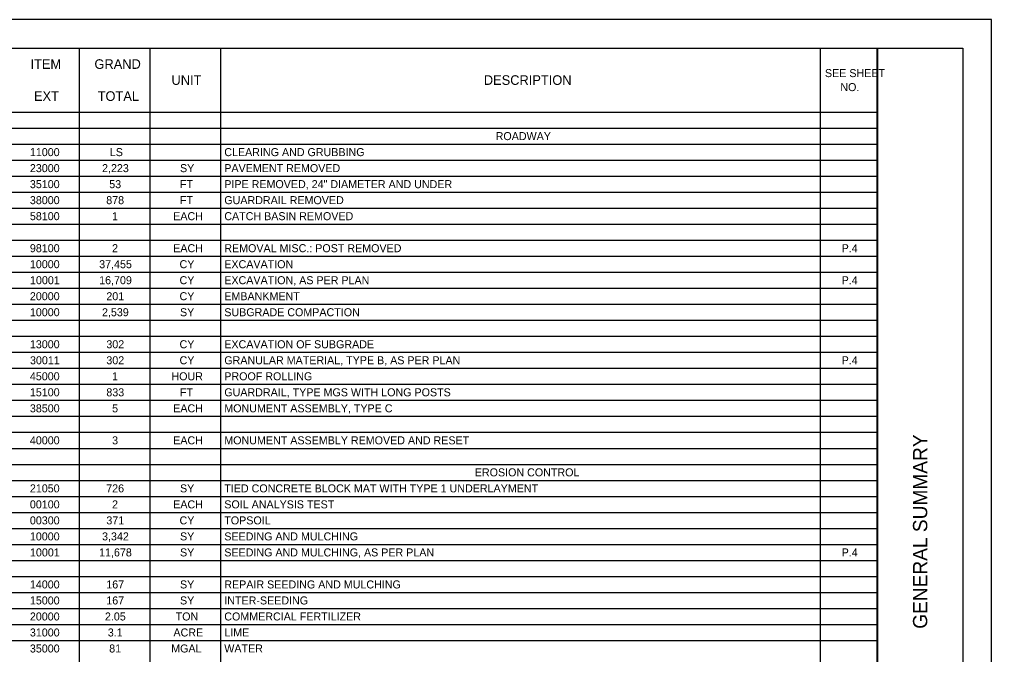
# Model space of a CAD drawing. Extents: x 0 to 34, y 0 to 22.
# Drawn here: x 16.99 to 34, y 10.89 to 22 of the extents above; entities that cross this region are included whole.
import ezdxf

# ---------------------------------------------------------------- set-up
doc = ezdxf.new("R2010")
doc.units = 0
for name, color, linetype in [('SH_Border', 7, 'Continuous'), ('SH_Cut_Line', 7, 'Continuous'), ('SH_Data', 7, 'Continuous'), ('SH_Text', 7, 'Continuous')]:
    doc.layers.add(name, color=color, linetype=linetype)

msp = doc.modelspace()

# ---------------------------------------------------------------- linework, layer by layer
at = {"layer": 'SH_Border'}
msp.add_line((32, 0.5), (32, 21.5), dxfattribs=at)
msp.add_lwpolyline([(1.5, 21.5), (33.5, 21.5), (33.5, 0.5), (1.5, 0.5)], close=True, dxfattribs=at)
at = {"layer": 'SH_Cut_Line'}
msp.add_lwpolyline([(0, 0), (34, 0), (34, 22), (0, 22)], close=True, dxfattribs=at)
at = {"layer": 'SH_Data'}
for p, q in [((1.5, 21.5), (32.004, 21.5)), ((18.036, 21.5), (18.036, 0.5)), ((19.272, 21.5), (19.272, 0.5)), ((20.507, 21.5), (20.507, 0.5)), ((30.999, 21.5), (30.999, 0.5)), ((32.004, 21.5), (32.004, 0.5)), ((1.5, 20.38), (32.004, 20.38)), ((1.5, 20.1), (32.004, 20.1)), ((1.5, 19.82), (32.004, 19.82)), ((1.5, 19.54), (32.004, 19.54)), ((1.5, 19.26), (32.004, 19.26)), ((1.5, 18.98), (32.004, 18.98)), ((1.5, 18.7), (32.004, 18.7)), ((1.5, 18.42), (32.004, 18.42)), ((1.5, 18.14), (32.004, 18.14)), ((1.5, 17.86), (32.004, 17.86)), ((1.5, 17.58), (32.004, 17.58)), ((1.5, 17.3), (32.004, 17.3)), ((1.5, 17.02), (32.004, 17.02)), ((1.5, 16.74), (32.004, 16.74)), ((1.5, 16.46), (32.004, 16.46)), ((1.5, 16.18), (32.004, 16.18)), ((1.5, 15.9), (32.004, 15.9)), ((1.5, 15.62), (32.004, 15.62)), ((1.5, 15.34), (32.004, 15.34)), ((1.5, 15.06), (32.004, 15.06)), ((1.5, 14.78), (32.004, 14.78)), ((1.5, 14.5), (32.004, 14.5)), ((1.5, 14.22), (32.004, 14.22)), ((1.5, 13.94), (32.004, 13.94)), ((1.5, 13.66), (32.004, 13.66)), ((1.5, 13.38), (32.004, 13.38)), ((1.5, 13.1), (32.004, 13.1)), ((1.5, 12.82), (32.004, 12.82)), ((1.5, 12.54), (32.004, 12.54)), ((1.5, 12.26), (32.004, 12.26)), ((1.5, 11.98), (32.004, 11.98)), ((1.5, 11.7), (32.004, 11.7)), ((1.5, 11.42), (32.004, 11.42)), ((1.5, 11.14), (32.004, 11.14))]:
    msp.add_line(p, q, dxfattribs=at)

# ---------------------------------------------------------------- texts
msp.add_text('GENERAL SUMMARY', height=0.25, rotation=90, dxfattribs=at).set_placement((32.875, 11.344))
at = {"layer": 'SH_Text'}
for s, height, p in [('ITEM', 0.168, (17.181, 21.136)), ('GRAND', 0.168, (18.301, 21.136)), ('SEE SHEET ', 0.14, (31.084, 20.992)), ('UNIT', 0.168, (19.649, 20.856)), ('DESCRIPTION', 0.168, (25.115, 20.856)), ('NO.', 0.14, (31.354, 20.747)), ('EXT', 0.168, (17.242, 20.576)), ('TOTAL', 0.168, (18.357, 20.576)), ('ROADWAY', 0.14, (25.322, 19.89)), ('11000', 0.14, (17.171, 19.61)), ('LS', 0.14, (18.57, 19.61)), ('CLEARING AND GRUBBING', 0.14, (20.573, 19.61)), ('23000', 0.14, (17.171, 19.33)), ('2,223', 0.14, (18.434, 19.33)), ('SY', 0.14, (19.798, 19.33)), ('PAVEMENT REMOVED', 0.14, (20.573, 19.33)), ('35100', 0.14, (17.171, 19.05)), ('53', 0.14, (18.56, 19.05)), ('FT', 0.14, (19.796, 19.05)), ('PIPE REMOVED, 24" DIAMETER AND UNDER', 0.14, (20.573, 19.05)), ('38000', 0.14, (17.171, 18.77)), ('878', 0.14, (18.507, 18.77)), ('FT', 0.14, (19.796, 18.77)), ('GUARDRAIL REMOVED', 0.14, (20.573, 18.77)), ('58100', 0.14, (17.171, 18.49)), ('1', 0.14, (18.609, 18.49)), ('EACH', 0.14, (19.679, 18.49)), ('CATCH BASIN REMOVED', 0.14, (20.573, 18.49)), ('98100', 0.14, (17.171, 17.93)), ('2', 0.14, (18.609, 17.93)), ('EACH', 0.14, (19.679, 17.93)), ('REMOVAL MISC.: POST REMOVED', 0.14, (20.573, 17.93)), ('P.4', 0.14, (31.377, 17.93)), ('10000', 0.14, (17.171, 17.65)), ('37,455', 0.14, (18.384, 17.65)), ('CY', 0.14, (19.79, 17.65)), ('EXCAVATION', 0.14, (20.573, 17.65)), ('10001', 0.14, (17.173, 17.37)), ('16,709', 0.14, (18.383, 17.37)), ('CY', 0.14, (19.79, 17.37)), ('EXCAVATION, AS PER PLAN', 0.14, (20.573, 17.37)), ('P.4', 0.14, (31.377, 17.37)), ('20000', 0.14, (17.171, 17.09)), ('201', 0.14, (18.509, 17.09)), ('CY', 0.14, (19.79, 17.09)), ('EMBANKMENT', 0.14, (20.573, 17.09)), ('10000', 0.14, (17.171, 16.81)), ('2,539', 0.14, (18.433, 16.81)), ('SY', 0.14, (19.798, 16.81)), ('SUBGRADE COMPACTION', 0.14, (20.573, 16.81)), ('13000', 0.14, (17.171, 16.25)), ('302', 0.14, (18.509, 16.25)), ('CY', 0.14, (19.79, 16.25)), ('EXCAVATION OF SUBGRADE', 0.14, (20.573, 16.25)), ('30011', 0.14, (17.173, 15.97)), ('302', 0.14, (18.509, 15.97)), ('CY', 0.14, (19.79, 15.97)), ('GRANULAR MATERIAL, TYPE B, AS PER PLAN', 0.14, (20.573, 15.97)), ('P.4', 0.14, (31.377, 15.97)), ('45000', 0.14, (17.171, 15.69)), ('1', 0.14, (18.609, 15.69)), ('HOUR', 0.14, (19.648, 15.69)), ('PROOF ROLLING', 0.14, (20.573, 15.69)), ('15100', 0.14, (17.171, 15.41)), ('833', 0.14, (18.509, 15.41)), ('FT', 0.14, (19.796, 15.41)), ('GUARDRAIL, TYPE MGS WITH LONG POSTS', 0.14, (20.573, 15.41)), ('38500', 0.14, (17.171, 15.13)), ('5', 0.14, (18.61, 15.13)), ('EACH', 0.14, (19.679, 15.13)), ('MONUMENT ASSEMBLY, TYPE C', 0.14, (20.573, 15.13)), ('40000', 0.14, (17.171, 14.57)), ('3', 0.14, (18.61, 14.57)), ('EACH', 0.14, (19.679, 14.57)), ('MONUMENT ASSEMBLY REMOVED AND RESET', 0.14, (20.573, 14.57)), ('EROSION CONTROL', 0.14, (24.957, 14.01)), ('21050', 0.14, (17.171, 13.73)), ('726', 0.14, (18.507, 13.73)), ('SY', 0.14, (19.798, 13.73)), ('TIED CONCRETE BLOCK MAT WITH TYPE 1 UNDERLAYMENT', 0.14, (20.573, 13.73)), ('00100', 0.14, (17.171, 13.45)), ('2', 0.14, (18.609, 13.45)), ('EACH', 0.14, (19.679, 13.45)), ('SOIL ANALYSIS TEST', 0.14, (20.573, 13.45)), ('00300', 0.14, (17.171, 13.17)), ('371', 0.14, (18.509, 13.17)), ('CY', 0.14, (19.79, 13.17)), ('TOPSOIL', 0.14, (20.573, 13.17)), ('10000', 0.14, (17.171, 12.89)), ('3,342', 0.14, (18.434, 12.89)), ('SY', 0.14, (19.798, 12.89)), ('SEEDING AND MULCHING', 0.14, (20.573, 12.89)), ('10001', 0.14, (17.173, 12.61)), ('11,678', 0.14, (18.382, 12.61)), ('SY', 0.14, (19.798, 12.61)), ('SEEDING AND MULCHING, AS PER PLAN', 0.14, (20.573, 12.61)), ('P.4', 0.14, (31.377, 12.61)), ('14000', 0.14, (17.171, 12.05)), ('167', 0.14, (18.508, 12.05)), ('SY', 0.14, (19.798, 12.05)), ('REPAIR SEEDING AND MULCHING', 0.14, (20.573, 12.05)), ('15000', 0.14, (17.171, 11.77)), ('167', 0.14, (18.508, 11.77)), ('SY', 0.14, (19.798, 11.77)), ('INTER-SEEDING', 0.14, (20.573, 11.77)), ('20000', 0.14, (17.171, 11.49)), ('2.05', 0.14, (18.484, 11.49)), ('TON', 0.14, (19.722, 11.49)), ('COMMERCIAL FERTILIZER', 0.14, (20.573, 11.49)), ('31000', 0.14, (17.171, 11.21)), ('3.1', 0.14, (18.534, 11.21)), ('ACRE', 0.14, (19.683, 11.21)), ('LIME', 0.14, (20.573, 11.21)), ('35000', 0.14, (17.171, 10.93)), ('81', 0.14, (18.559, 10.93)), ('MGAL', 0.14, (19.644, 10.93)), ('WATER', 0.14, (20.573, 10.93))]:
    msp.add_text(s, height=height, dxfattribs=at).set_placement(p)

doc.saveas('drawing.dxf')
